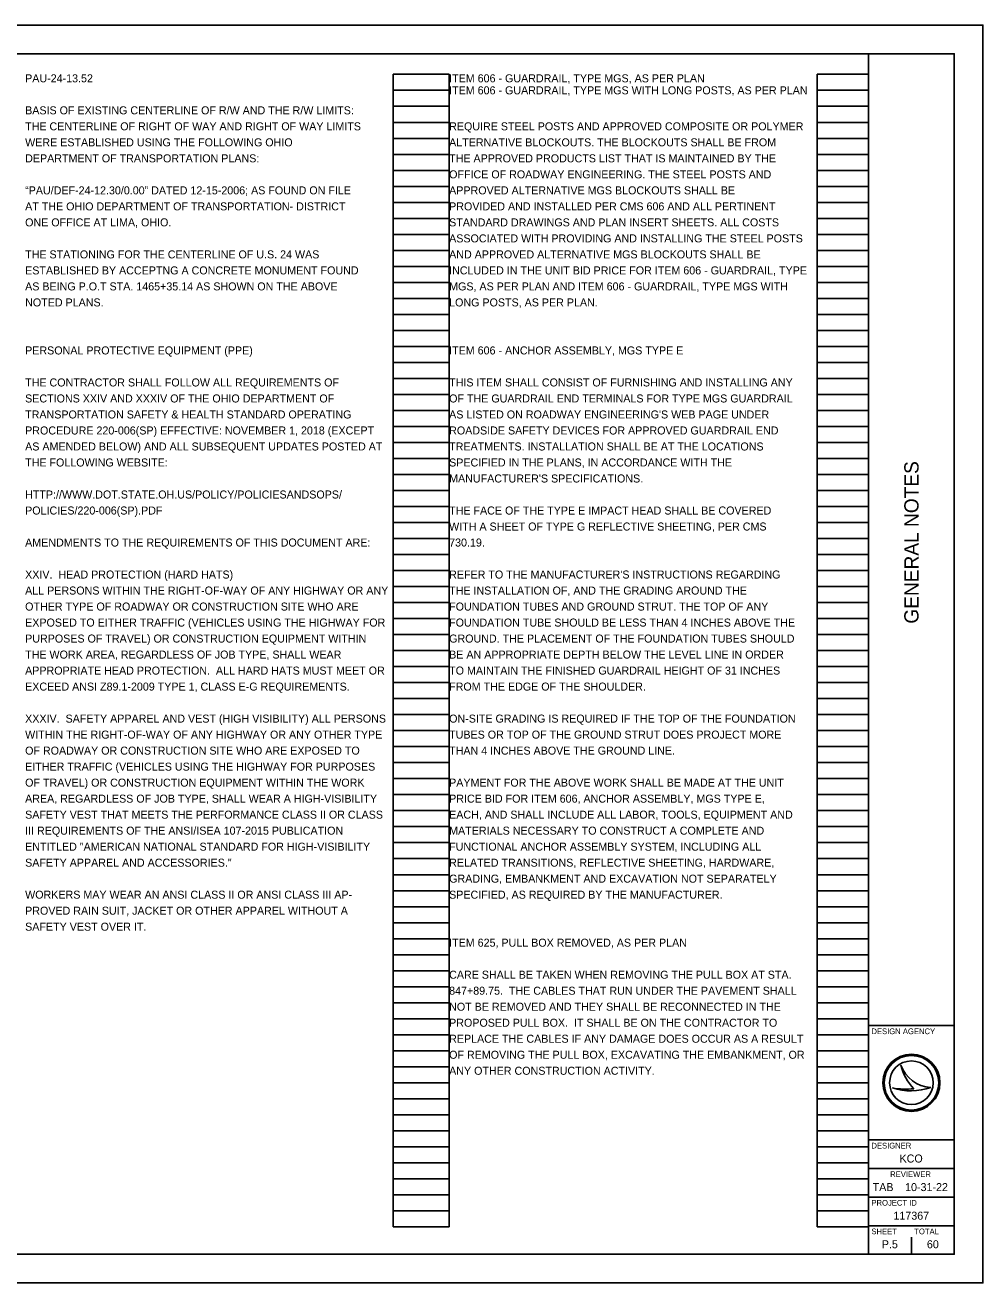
# Model space of a CAD drawing. Extents: x 0 to 34, y 0 to 22.
# Drawn here: x 17.24 to 34, y 0 to 22 of the extents above; entities that cross this region are included whole.
import ezdxf

# ---------------------------------------------------------------- set-up
doc = ezdxf.new("R2010")
doc.units = 0
for name, color, linetype in [('SH_Border', 7, 'Continuous'), ('SH_Cut_Line', 7, 'Continuous'), ('SH_Data', 7, 'Continuous'), ('SH_Text', 7, 'Continuous')]:
    doc.layers.add(name, color=color, linetype=linetype)

msp = doc.modelspace()

# ---------------------------------------------------------------- linework, layer by layer
at = {"layer": 'SH_Border'}
for p, q in [((32, 0.5), (32, 21.5)), ((32, 4.5), (33.5, 4.5)), ((32, 2.5), (33.5, 2.5)), ((32, 2), (33.5, 2)), ((32, 1.5), (33.5, 1.5)), ((32, 1), (33.5, 1))]:
    msp.add_line(p, q, dxfattribs=at)
msp.add_lwpolyline([(1.5, 21.5), (33.5, 21.5), (33.5, 0.5), (1.5, 0.5)], close=True, dxfattribs=at)
at = {"layer": 'SH_Cut_Line'}
msp.add_lwpolyline([(0, 0), (34, 0), (34, 22), (0, 22)], close=True, dxfattribs=at)
at = {"layer": 'SH_Data'}
for p, q in [((23.68, 0.98), (23.68, 21.14)), ((23.68, 21.14), (24.66, 21.14)), ((24.66, 0.98), (24.66, 21.14)), ((31.1, 0.98), (31.1, 21.14)), ((31.1, 21.14), (32, 21.14)), ((32, 0.98), (32, 21.14)), ((23.68, 20.86), (24.66, 20.86)), ((31.1, 20.86), (32, 20.86)), ((23.68, 20.58), (24.66, 20.58)), ((31.1, 20.58), (32, 20.58)), ((23.68, 20.3), (24.66, 20.3)), ((31.1, 20.3), (32, 20.3)), ((23.68, 20.02), (24.66, 20.02)), ((31.1, 20.02), (32, 20.02)), ((23.68, 19.74), (24.66, 19.74)), ((31.1, 19.74), (32, 19.74)), ((23.68, 19.46), (24.66, 19.46)), ((31.1, 19.46), (32, 19.46)), ((23.68, 19.18), (24.66, 19.18)), ((31.1, 19.18), (32, 19.18)), ((23.68, 18.9), (24.66, 18.9)), ((31.1, 18.9), (32, 18.9)), ((23.68, 18.62), (24.66, 18.62)), ((31.1, 18.62), (32, 18.62)), ((23.68, 18.34), (24.66, 18.34)), ((31.1, 18.34), (32, 18.34)), ((23.68, 18.06), (24.66, 18.06)), ((31.1, 18.06), (32, 18.06)), ((23.68, 17.78), (24.66, 17.78)), ((31.1, 17.78), (32, 17.78)), ((23.68, 17.5), (24.66, 17.5)), ((31.1, 17.5), (32, 17.5)), ((23.68, 17.22), (24.66, 17.22)), ((31.1, 17.22), (32, 17.22)), ((23.68, 16.94), (24.66, 16.94)), ((31.1, 16.94), (32, 16.94)), ((23.68, 16.66), (24.66, 16.66)), ((31.1, 16.66), (32, 16.66)), ((23.68, 16.38), (24.66, 16.38)), ((31.1, 16.38), (32, 16.38)), ((23.68, 16.1), (24.66, 16.1)), ((31.1, 16.1), (32, 16.1)), ((23.68, 15.82), (24.66, 15.82)), ((31.1, 15.82), (32, 15.82)), ((23.68, 15.54), (24.66, 15.54)), ((31.1, 15.54), (32, 15.54)), ((23.68, 15.26), (24.66, 15.26)), ((31.1, 15.26), (32, 15.26)), ((23.68, 14.98), (24.66, 14.98)), ((31.1, 14.98), (32, 14.98)), ((23.68, 14.7), (24.66, 14.7)), ((31.1, 14.7), (32, 14.7)), ((23.68, 14.42), (24.66, 14.42)), ((31.1, 14.42), (32, 14.42)), ((23.68, 14.14), (24.66, 14.14)), ((31.1, 14.14), (32, 14.14)), ((23.68, 13.86), (24.66, 13.86)), ((31.1, 13.86), (32, 13.86)), ((23.68, 13.58), (24.66, 13.58)), ((31.1, 13.58), (32, 13.58)), ((23.68, 13.3), (24.66, 13.3)), ((31.1, 13.3), (32, 13.3)), ((23.68, 13.02), (24.66, 13.02)), ((31.1, 13.02), (32, 13.02)), ((23.68, 12.74), (24.66, 12.74)), ((31.1, 12.74), (32, 12.74)), ((23.68, 12.46), (24.66, 12.46)), ((31.1, 12.46), (32, 12.46)), ((23.68, 12.18), (24.66, 12.18)), ((31.1, 12.18), (32, 12.18)), ((23.68, 11.9), (24.66, 11.9)), ((31.1, 11.9), (32, 11.9)), ((23.68, 11.62), (24.66, 11.62)), ((31.1, 11.62), (32, 11.62)), ((23.68, 11.34), (24.66, 11.34)), ((31.1, 11.34), (32, 11.34)), ((23.68, 11.06), (24.66, 11.06)), ((31.1, 11.06), (32, 11.06)), ((23.68, 10.78), (24.66, 10.78)), ((31.1, 10.78), (32, 10.78)), ((23.68, 10.5), (24.66, 10.5)), ((31.1, 10.5), (32, 10.5)), ((23.68, 10.22), (24.66, 10.22)), ((31.1, 10.22), (32, 10.22)), ((23.68, 9.94), (24.66, 9.94)), ((31.1, 9.94), (32, 9.94)), ((23.68, 9.66), (24.66, 9.66)), ((31.1, 9.66), (32, 9.66)), ((23.68, 9.38), (24.66, 9.38)), ((31.1, 9.38), (32, 9.38)), ((23.68, 9.1), (24.66, 9.1)), ((31.1, 9.1), (32, 9.1)), ((23.68, 8.82), (24.66, 8.82)), ((31.1, 8.82), (32, 8.82)), ((23.68, 8.54), (24.66, 8.54)), ((31.1, 8.54), (32, 8.54)), ((23.68, 8.26), (24.66, 8.26)), ((31.1, 8.26), (32, 8.26)), ((23.68, 7.98), (24.66, 7.98)), ((31.1, 7.98), (32, 7.98)), ((23.68, 7.7), (24.66, 7.7)), ((31.1, 7.7), (32, 7.7)), ((23.68, 7.42), (24.66, 7.42)), ((31.1, 7.42), (32, 7.42)), ((23.68, 7.14), (24.66, 7.14)), ((31.1, 7.14), (32, 7.14)), ((23.68, 6.86), (24.66, 6.86)), ((31.1, 6.86), (32, 6.86)), ((23.68, 6.58), (24.66, 6.58)), ((31.1, 6.58), (32, 6.58)), ((23.68, 6.3), (24.66, 6.3)), ((31.1, 6.3), (32, 6.3)), ((23.68, 6.02), (24.66, 6.02)), ((31.1, 6.02), (32, 6.02)), ((23.68, 5.74), (24.66, 5.74)), ((31.1, 5.74), (32, 5.74)), ((23.68, 5.46), (24.66, 5.46)), ((31.1, 5.46), (32, 5.46)), ((23.68, 5.18), (24.66, 5.18)), ((31.1, 5.18), (32, 5.18)), ((23.68, 4.9), (24.66, 4.9)), ((31.1, 4.9), (32, 4.9)), ((23.68, 4.62), (24.66, 4.62)), ((31.1, 4.62), (32, 4.62)), ((23.68, 4.34), (24.66, 4.34)), ((31.1, 4.34), (32, 4.34)), ((23.68, 4.06), (24.66, 4.06)), ((31.1, 4.06), (32, 4.06)), ((23.68, 3.78), (24.66, 3.78)), ((31.1, 3.78), (32, 3.78)), ((32.567, 3.81), (32.567, 3.81)), ((23.68, 3.5), (24.66, 3.5)), ((31.1, 3.5), (32, 3.5)), ((32.417, 3.41), (32.417, 3.41)), ((32.75, 3.5), (32.75, 3.5)), ((33.087, 3.419), (33.087, 3.419)), ((23.68, 3.22), (24.66, 3.22)), ((31.1, 3.22), (32, 3.22)), ((23.68, 2.94), (24.66, 2.94)), ((31.1, 2.94), (32, 2.94)), ((23.68, 2.66), (24.66, 2.66)), ((31.1, 2.66), (32, 2.66)), ((23.68, 2.38), (24.66, 2.38)), ((31.1, 2.38), (32, 2.38)), ((23.68, 2.1), (24.66, 2.1)), ((31.1, 2.1), (32, 2.1)), ((23.68, 1.82), (24.66, 1.82)), ((31.1, 1.82), (32, 1.82)), ((23.68, 1.54), (24.66, 1.54)), ((31.1, 1.54), (32, 1.54)), ((23.68, 1.26), (24.66, 1.26)), ((31.1, 1.26), (32, 1.26)), ((23.68, 0.98), (24.66, 0.98)), ((31.1, 0.98), (32, 0.98)), ((32.375, 0.675), (32.375, 0.675)), ((32.75, 0.5), (32.75, 0.8))]:
    msp.add_line(p, q, dxfattribs=at)
for radius in [0.5, 0.477, 0.477, 0.382]:
    msp.add_circle((32.75, 3.5), radius, dxfattribs=at)
for centre, radius, start, end in [((33.116, 3.998), 0.58, 198.9257, 198.9319), ((33.347, 3.97), 0.796, 191.6379, 191.6421), ((33.116, 3.998), 0.58, 198.9319, 267.1657), ((33.347, 3.97), 0.796, 191.6421, 226.0947), ((32.739, 4.37), 1.013, 251.4576, 290.0832), ((32.648, 4.654), 1.266, 259.4964, 259.4995), ((32.739, 4.37), 1.013, 251.4527, 251.4576), ((32.648, 4.654), 1.266, 259.4995, 276.6672)]:
    msp.add_arc(centre, radius, start, end, dxfattribs=at)

# ---------------------------------------------------------------- texts
msp.add_text('GENERAL NOTES', height=0.25, rotation=90, dxfattribs=at).set_placement((32.875, 11.531))
for s, height, p in [('DESIGN AGENCY', 0.1, (32.05, 4.35)), ('DESIGNER', 0.1, (32.05, 2.35)), ('KCO', 0.14, (32.542, 2.105)), ('REVIEWER', 0.1, (32.378, 1.85)), ('TAB', 0.14, (32.072, 1.605)), ('10-31-22', 0.14, (32.639, 1.605)), ('PROJECT ID', 0.1, (32.05, 1.35)), ('117367', 0.14, (32.435, 1.105)), ('SHEET', 0.1, (32.05, 0.85)), ('TOTAL', 0.1, (32.8, 0.85)), ('P.5', 0.14, (32.232, 0.605)), ('60', 0.14, (33.021, 0.605))]:
    msp.add_text(s, height=height, dxfattribs=at).set_placement(p)
at = {"layer": 'SH_Text'}
for s, p in [('PAU-24-13.52', (17.24, 21)), ('ITEM 606 - GUARDRAIL, TYPE MGS, AS PER PLAN', (24.66, 21)), ('ITEM 606 - GUARDRAIL, TYPE MGS WITH LONG POSTS, AS PER PLAN', (24.66, 20.79)), ('BASIS OF EXISTING CENTERLINE OF R/W AND THE R/W LIMITS:', (17.24, 20.44)), ('THE CENTERLINE OF RIGHT OF WAY AND RIGHT OF WAY LIMITS ', (17.24, 20.16)), ('REQUIRE STEEL POSTS AND APPROVED COMPOSITE OR POLYMER ', (24.66, 20.16)), ('WERE ESTABLISHED USING THE FOLLOWING OHIO ', (17.24, 19.88)), ('ALTERNATIVE BLOCKOUTS. THE BLOCKOUTS SHALL BE FROM ', (24.66, 19.88)), ('DEPARTMENT OF TRANSPORTATION PLANS:', (17.24, 19.6)), ('THE APPROVED PRODUCTS LIST THAT IS MAINTAINED BY THE ', (24.66, 19.6)), ('OFFICE OF ROADWAY ENGINEERING. THE STEEL POSTS AND ', (24.66, 19.32)), ('“PAU/DEF-24-12.30/0.00” DATED 12-15-2006; AS FOUND ON FILE ', (17.24, 19.04)), ('APPROVED ALTERNATIVE MGS BLOCKOUTS SHALL BE', (24.66, 19.04)), ('AT THE OHIO DEPARTMENT OF TRANSPORTATION- DISTRICT ', (17.24, 18.76)), ('PROVIDED AND INSTALLED PER CMS 606 AND ALL PERTINENT', (24.66, 18.76)), ('ONE OFFICE AT LIMA, OHIO.', (17.24, 18.48)), ('STANDARD DRAWINGS AND PLAN INSERT SHEETS. ALL COSTS', (24.66, 18.48)), ('ASSOCIATED WITH PROVIDING AND INSTALLING THE STEEL POSTS', (24.66, 18.2)), ('THE STATIONING FOR THE CENTERLINE OF U.S. 24 WAS ', (17.24, 17.92)), ('AND APPROVED ALTERNATIVE MGS BLOCKOUTS SHALL BE ', (24.66, 17.92)), ('ESTABLISHED BY ACCEPTNG A CONCRETE MONUMENT FOUND ', (17.24, 17.64)), ('INCLUDED IN THE UNIT BID PRICE FOR ITEM 606 - GUARDRAIL, TYPE ', (24.66, 17.64)), ('AS BEING P.O.T STA. 1465+35.14 AS SHOWN ON THE ABOVE ', (17.24, 17.36)), ('MGS, AS PER PLAN AND ITEM 606 - GUARDRAIL, TYPE MGS WITH ', (24.66, 17.36)), ('NOTED PLANS.', (17.24, 17.08)), ('LONG POSTS, AS PER PLAN.', (24.66, 17.08)), ('PERSONAL PROTECTIVE EQUIPMENT (PPE)', (17.24, 16.24)), ('ITEM 606 - ANCHOR ASSEMBLY, MGS TYPE E', (24.66, 16.24)), ('THE CONTRACTOR SHALL FOLLOW ALL REQUIREMENTS OF ', (17.24, 15.68)), ('THIS ITEM SHALL CONSIST OF FURNISHING AND INSTALLING ANY', (24.66, 15.68)), ('SECTIONS XXIV AND XXXIV OF THE OHIO DEPARTMENT OF ', (17.24, 15.4)), ('OF THE GUARDRAIL END TERMINALS FOR TYPE MGS GUARDRAIL', (24.66, 15.4)), ('TRANSPORTATION SAFETY & HEALTH STANDARD OPERATING ', (17.24, 15.12)), ("AS LISTED ON ROADWAY ENGINEERING'S WEB PAGE UNDER", (24.66, 15.12)), ('PROCEDURE 220-006(SP) EFFECTIVE: NOVEMBER 1, 2018 (EXCEPT ', (17.24, 14.84)), ('ROADSIDE SAFETY DEVICES FOR APPROVED GUARDRAIL END', (24.66, 14.84)), ('AS AMENDED BELOW) AND ALL SUBSEQUENT UPDATES POSTED AT ', (17.24, 14.56)), ('TREATMENTS. INSTALLATION SHALL BE AT THE LOCATIONS', (24.66, 14.56)), ('THE FOLLOWING WEBSITE: ', (17.24, 14.28)), ('SPECIFIED IN THE PLANS, IN ACCORDANCE WITH THE', (24.66, 14.28)), ("MANUFACTURER'S SPECIFICATIONS.", (24.66, 14)), ('HTTP://WWW.DOT.STATE.OH.US/POLICY/POLICIESANDSOPS/', (17.24, 13.72)), ('POLICIES/220-006(SP).PDF', (17.24, 13.44)), ('THE FACE OF THE TYPE E IMPACT HEAD SHALL BE COVERED', (24.66, 13.44)), ('WITH A SHEET OF TYPE G REFLECTIVE SHEETING, PER CMS', (24.66, 13.16)), ('AMENDMENTS TO THE REQUIREMENTS OF THIS DOCUMENT ARE:', (17.24, 12.88)), ('730.19.', (24.66, 12.88)), ('XXIV.  HEAD PROTECTION (HARD HATS)', (17.24, 12.32)), ("REFER TO THE MANUFACTURER'S INSTRUCTIONS REGARDING", (24.66, 12.32)), ('ALL PERSONS WITHIN THE RIGHT-OF-WAY OF ANY HIGHWAY OR ANY ', (17.24, 12.04)), ('THE INSTALLATION OF, AND THE GRADING AROUND THE', (24.66, 12.04)), ('OTHER TYPE OF ROADWAY OR CONSTRUCTION SITE WHO ARE ', (17.24, 11.76)), ('FOUNDATION TUBES AND GROUND STRUT. THE TOP OF ANY', (24.66, 11.76)), ('EXPOSED TO EITHER TRAFFIC (VEHICLES USING THE HIGHWAY FOR ', (17.24, 11.48)), ('FOUNDATION TUBE SHOULD BE LESS THAN 4 INCHES ABOVE THE', (24.66, 11.48)), ('PURPOSES OF TRAVEL) OR CONSTRUCTION EQUIPMENT WITHIN ', (17.24, 11.2)), ('GROUND. THE PLACEMENT OF THE FOUNDATION TUBES SHOULD', (24.66, 11.2)), ('THE WORK AREA, REGARDLESS OF JOB TYPE, SHALL WEAR ', (17.24, 10.92)), ('BE AN APPROPRIATE DEPTH BELOW THE LEVEL LINE IN ORDER', (24.66, 10.92)), ('APPROPRIATE HEAD PROTECTION.  ALL HARD HATS MUST MEET OR ', (17.24, 10.64)), ('TO MAINTAIN THE FINISHED GUARDRAIL HEIGHT OF 31 INCHES', (24.66, 10.64)), ('EXCEED ANSI Z89.1-2009 TYPE 1, CLASS E-G REQUIREMENTS. ', (17.24, 10.36)), ('FROM THE EDGE OF THE SHOULDER.', (24.66, 10.36)), ('XXXIV.  SAFETY APPAREL AND VEST (HIGH VISIBILITY) ALL PERSONS ', (17.24, 9.8)), ('ON-SITE GRADING IS REQUIRED IF THE TOP OF THE FOUNDATION', (24.66, 9.8)), ('WITHIN THE RIGHT-OF-WAY OF ANY HIGHWAY OR ANY OTHER TYPE ', (17.24, 9.52)), ('TUBES OR TOP OF THE GROUND STRUT DOES PROJECT MORE', (24.66, 9.52)), ('OF ROADWAY OR CONSTRUCTION SITE WHO ARE EXPOSED TO ', (17.24, 9.24)), ('THAN 4 INCHES ABOVE THE GROUND LINE.', (24.66, 9.24)), ('EITHER TRAFFIC (VEHICLES USING THE HIGHWAY FOR PURPOSES ', (17.24, 8.96)), ('OF TRAVEL) OR CONSTRUCTION EQUIPMENT WITHIN THE WORK ', (17.24, 8.68)), ('PAYMENT FOR THE ABOVE WORK SHALL BE MADE AT THE UNIT', (24.66, 8.68)), ('AREA, REGARDLESS OF JOB TYPE, SHALL WEAR A HIGH-VISIBILITY ', (17.24, 8.4)), ('PRICE BID FOR ITEM 606, ANCHOR ASSEMBLY, MGS TYPE E,', (24.66, 8.4)), ('SAFETY VEST THAT MEETS THE PERFORMANCE CLASS II OR CLASS ', (17.24, 8.12)), ('EACH, AND SHALL INCLUDE ALL LABOR, TOOLS, EQUIPMENT AND', (24.66, 8.12)), ('III REQUIREMENTS OF THE ANSI/ISEA 107-2015 PUBLICATION ', (17.24, 7.84)), ('MATERIALS NECESSARY TO CONSTRUCT A COMPLETE AND', (24.66, 7.84)), ('ENTITLED "AMERICAN NATIONAL STANDARD FOR HIGH-VISIBILITY ', (17.24, 7.56)), ('FUNCTIONAL ANCHOR ASSEMBLY SYSTEM, INCLUDING ALL', (24.66, 7.56)), ('SAFETY APPAREL AND ACCESSORIES."', (17.24, 7.28)), ('RELATED TRANSITIONS, REFLECTIVE SHEETING, HARDWARE,', (24.66, 7.28)), ('GRADING, EMBANKMENT AND EXCAVATION NOT SEPARATELY', (24.66, 7)), ('WORKERS MAY WEAR AN ANSI CLASS II OR ANSI CLASS III AP-', (17.24, 6.72)), ('SPECIFIED, AS REQUIRED BY THE MANUFACTURER.', (24.66, 6.72)), ('PROVED RAIN SUIT, JACKET OR OTHER APPAREL WITHOUT A ', (17.24, 6.44)), ('SAFETY VEST OVER IT.  ', (17.24, 6.16)), ('ITEM 625, PULL BOX REMOVED, AS PER PLAN', (24.66, 5.88)), ('CARE SHALL BE TAKEN WHEN REMOVING THE PULL BOX AT STA. ', (24.66, 5.32)), ('847+89.75.  THE CABLES THAT RUN UNDER THE PAVEMENT SHALL ', (24.66, 5.04)), ('NOT BE REMOVED AND THEY SHALL BE RECONNECTED IN THE ', (24.66, 4.76)), ('PROPOSED PULL BOX.  IT SHALL BE ON THE CONTRACTOR TO ', (24.66, 4.48)), ('REPLACE THE CABLES IF ANY DAMAGE DOES OCCUR AS A RESULT ', (24.66, 4.2)), ('OF REMOVING THE PULL BOX, EXCAVATING THE EMBANKMENT, OR ', (24.66, 3.92)), ('ANY OTHER CONSTRUCTION ACTIVITY.', (24.66, 3.64))]:
    msp.add_text(s, height=0.14, dxfattribs=at).set_placement(p)

doc.saveas('drawing.dxf')
